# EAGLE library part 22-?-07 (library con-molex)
CONNECTOR wire to board 2.54 mm (.1 inch) pitch header
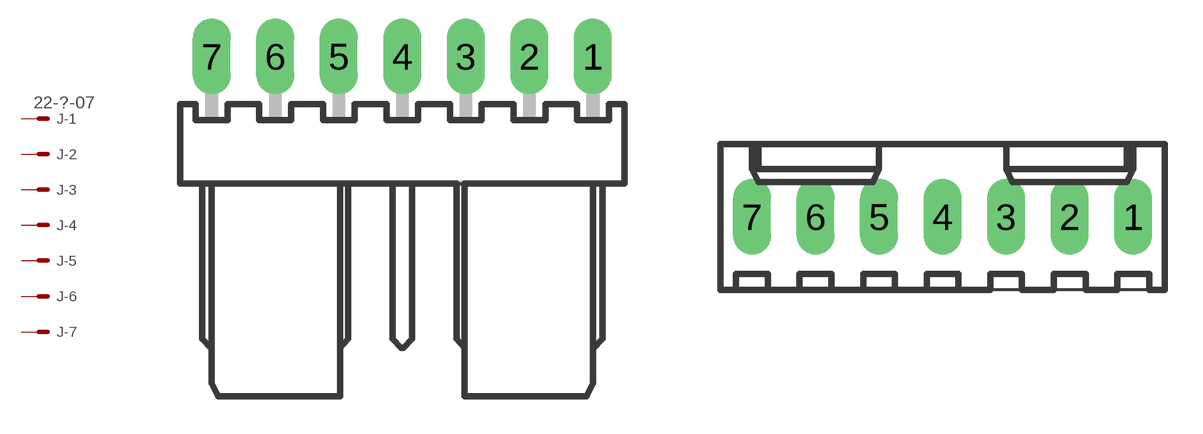
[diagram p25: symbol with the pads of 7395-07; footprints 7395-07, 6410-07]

Designator prefix J; gates -1=MV -2=M -3=M -4=M -5=M -6=M -7=M

## 22-05-7078-07 (OC_FARNELL: unknown; OC_NEWARK: unknown)  [7395-07]
1  -1:S  pas
2  -2:S  pas
3  -3:S  pas
4  -4:S  pas
5  -5:S  pas
6  -6:S  pas
7  -7:S  pas

## 22-27-2071-07 (OC_FARNELL: unknown; OC_NEWARK: unknown)  [6410-07]
Pads as for 7395-07

## Footprint 7395-07 (pad centres in mm)
MOLEX 2.54mm KK RA CONNECTOR Fixed Orientation
drill 1.016 long: 1 7.62,0; 2 5.08,0; 3 2.54,0; 4 0,0; 5 -2.54,0; 6 -5.08,0; 7 -7.62,0

## Footprint 6410-07 (pad centres in mm)
MOLEX 2.54mm KK CONNECTOR
drill 1.016 long: 1 7.62,0; 2 5.08,0; 3 2.54,0; 4 0,0; 5 -2.54,0; 6 -5.08,0; 7 -7.62,0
